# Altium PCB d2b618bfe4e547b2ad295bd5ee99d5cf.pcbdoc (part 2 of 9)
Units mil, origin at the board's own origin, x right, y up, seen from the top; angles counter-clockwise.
Board outline 5129 x 4161 mil, 8 copper layers (Top Layer, GND1, 内层2, VCC, 内层4, Inner5, GND2, Bottom Layer); 491 components, 452 nets, 2562 pads, 1124 vias.
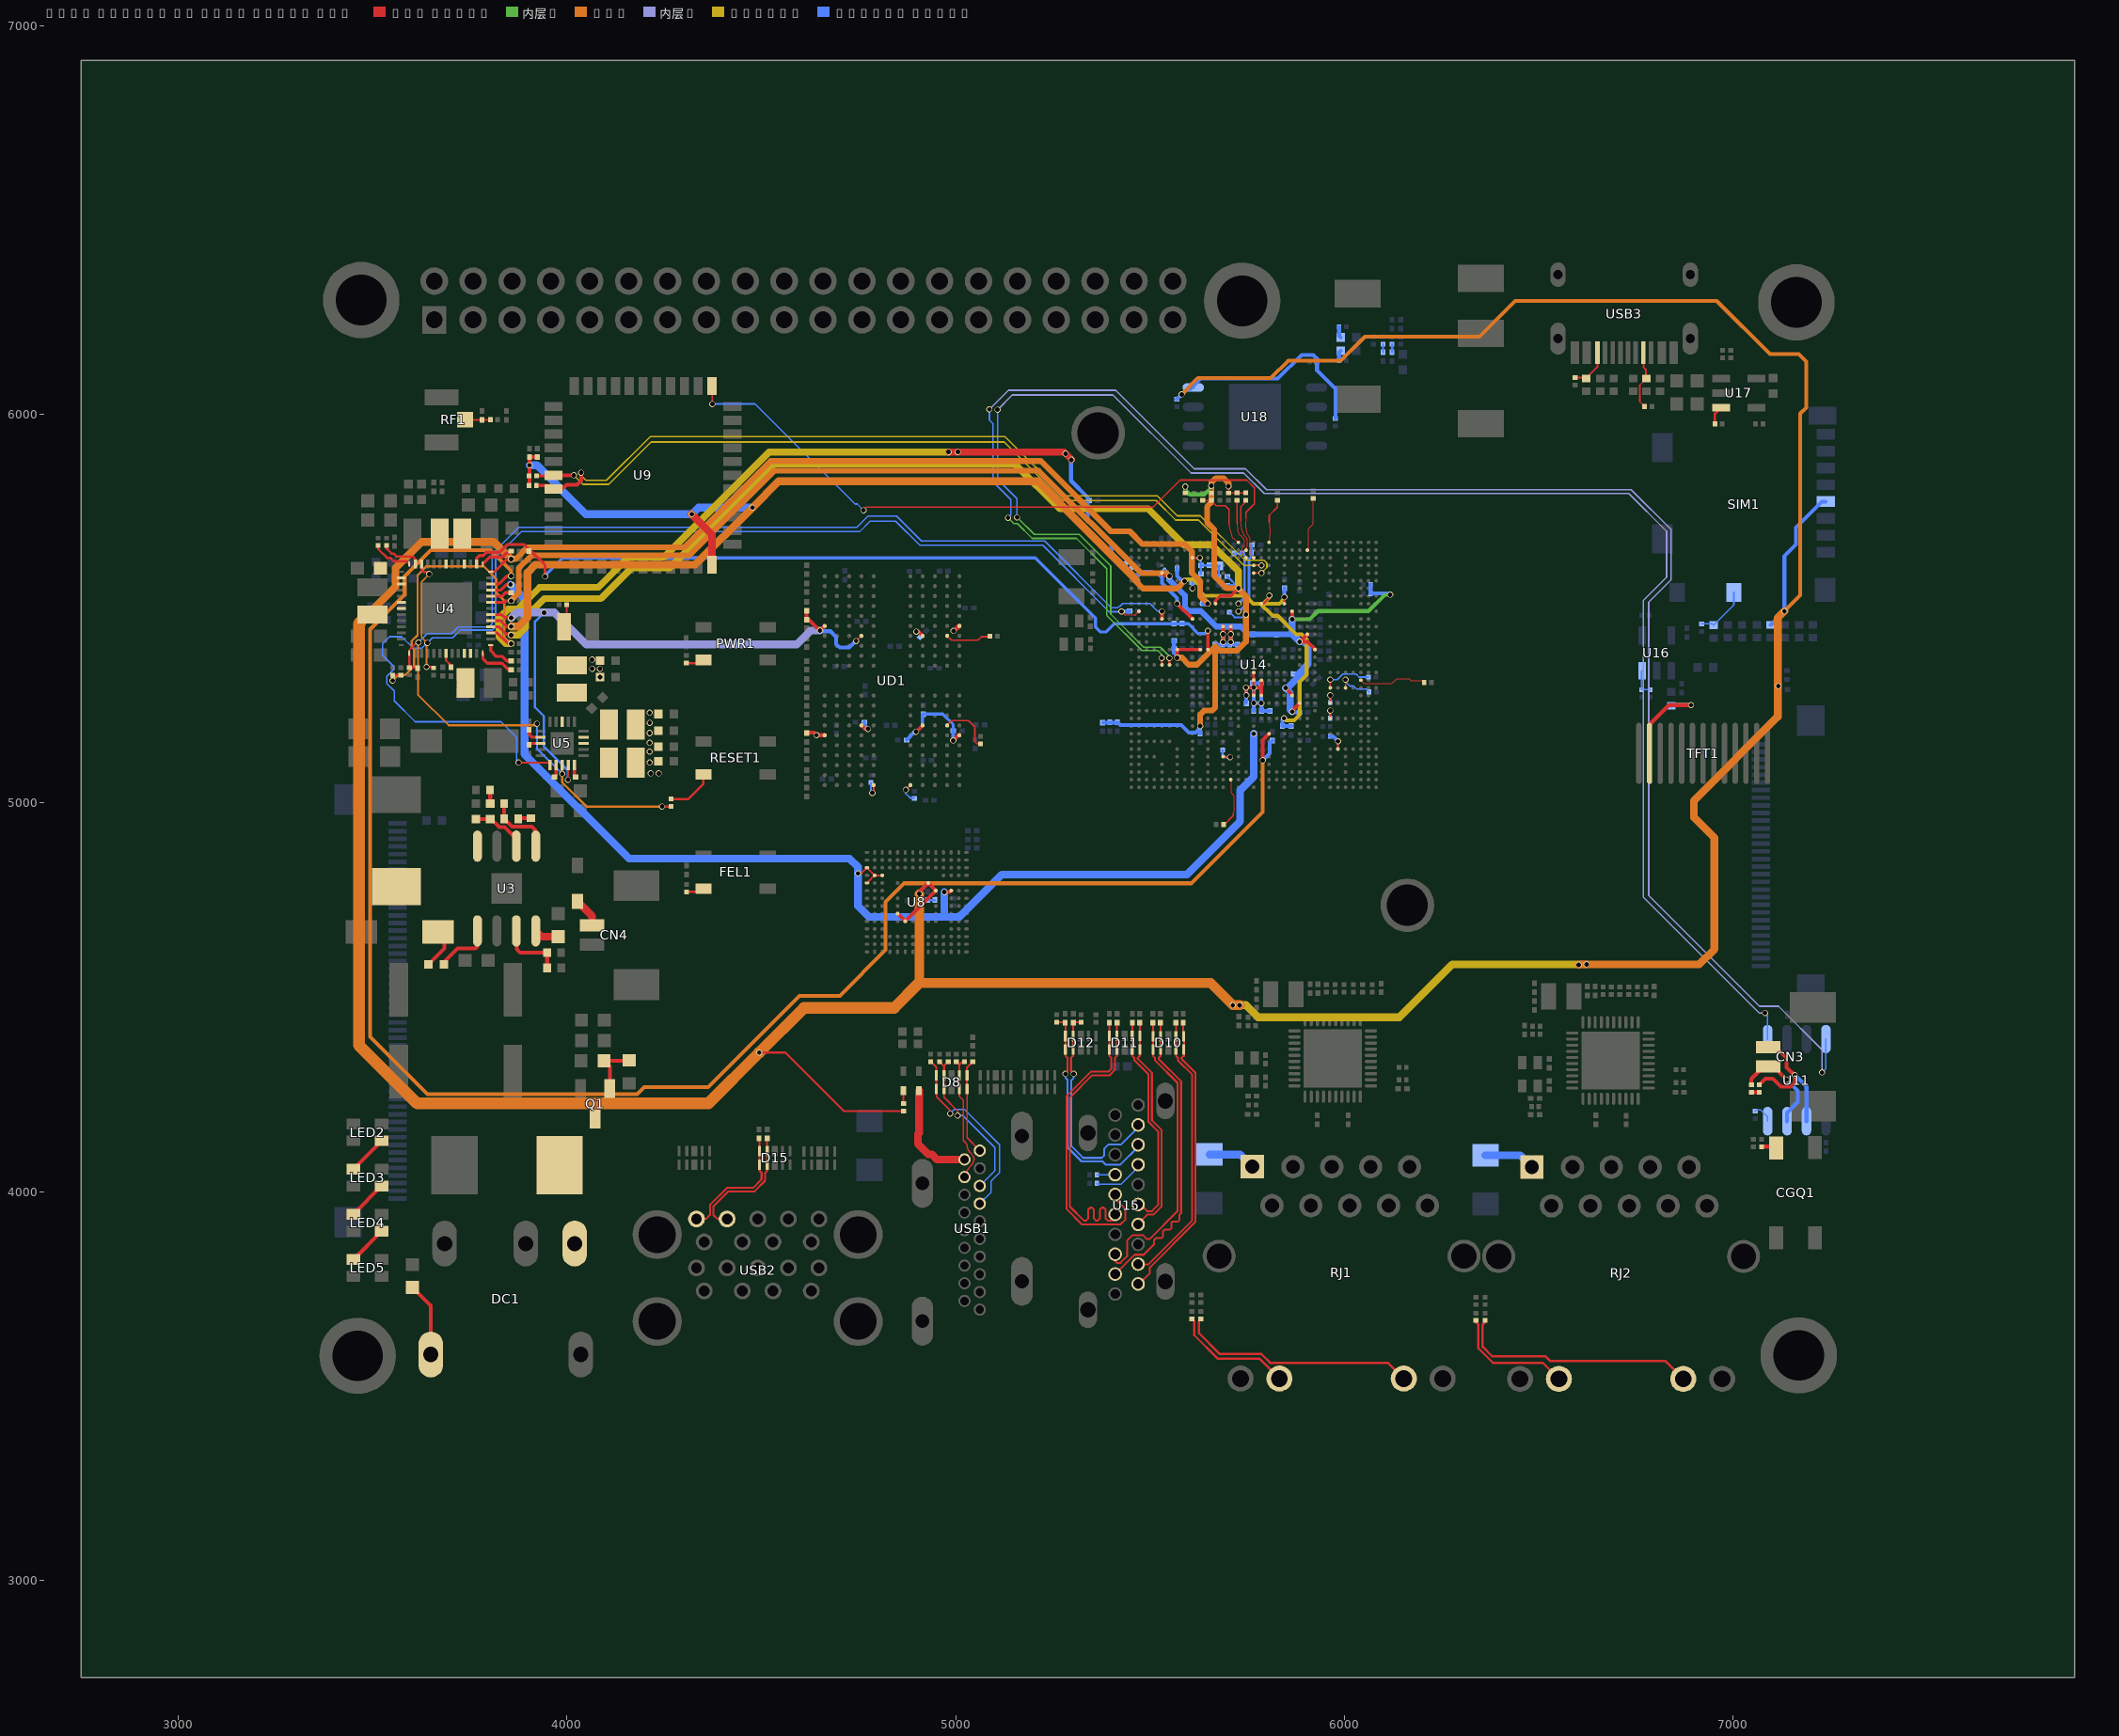
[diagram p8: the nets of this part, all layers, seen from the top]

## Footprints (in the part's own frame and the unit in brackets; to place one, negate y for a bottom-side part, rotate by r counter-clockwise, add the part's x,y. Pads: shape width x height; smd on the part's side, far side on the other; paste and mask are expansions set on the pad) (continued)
SOD-323_L1.8-W1.3-LS2.5-RD [mm]
  rect 1x0.75 smd: 1(-1.173,0) 2(1.173,0)
  silkscreen extent -1.08,-0.8 0.9,0.8
"SOD-523_L1.2-W0.8-LS1.6-RD-1 NSK" [mm]
  rect 0.6x0.36 smd: 1(-0.635,0) 2(0.635,0)
  silkscreen extent -0.13,-0.13 -0.13,0.13
SOIC-8_L5.0-W4.0-P1.27-LS6.0-BL-EP2.0 [mm]
  oval 0.574x2.038 smd: 1(-1.905,-2.769) 2(-0.635,-2.769) 3(0.635,-2.769) 4(1.905,-2.769) 5(1.905,2.769) 6(0.635,2.769) 7(-0.635,2.769) 8(-1.905,2.769)
  rect 2x2 smd: 9(0,0)
  silkscreen extent -2.79,-2.92 2.53,1.52
SOP-8_L4.9-W3.9-P1.27-LS6.0-BL [mm]
  oval 0.63x1.865 smd: 1(-1.905,-2.682) 2(-0.635,-2.682) 3(0.635,-2.682) 4(1.905,-2.682) 5(1.905,2.682) 6(0.635,2.682) 7(-0.635,2.682) 8(-1.905,2.682)
  silkscreen extent -2.82,-2.83 2.58,1.52
SOT-23-3_L2.9-W1.3-P1.90-LS2.4-BR [mm]
  rect 1.25x0.7 smd: 1(1,-0.95) 2(1,0.95) 3(-1,0)
  silkscreen extent -0.73,-1.53 0.73,1.53
SOT-23-5_L3.0-W1.7-P0.95-LS2.8-BL [mm]
  rect 0.49x1.157 smd: 1(-0.95,-1.154) 2(0,-1.154) 3(0.95,-1.154)
  rect 0.49x1.175 smd: 4(0.95,1.154) 5(-0.95,1.154)
  silkscreen extent -1.8,-1.29 1.53,0.85
SW-SMD_4P-L4.2-W3.4-P2.15-LS4.5-TL [mm]
  rect 1.05x0.7 smd: 1(-2.1,1.075) 2(2.1,1.075) 3(-2.1,-1.075) 4(2.1,-1.075)
  silkscreen extent -2.2,-1.69 2.2,1.71
T527-BGA664 [mm]
  round 0.239 smd: A1(-8,8) A2(-7.5,8) A3(-7,8) A4(-6.5,8) A5(-6,8) A6(-5.5,8) A8(-4.5,8) A10(-3.5,8) A12(-2.5,8) A14(-1.5,8) A16(-0.5,8) A18(0.5,8) A20(1.5,8) A22(2.5,8) A24(3.5,8) A26(4.5,8) A28(5.5,8) A29(6,8) A30(6.5,8) A31(7,8) A32(7.5,8) A33(8,8) AA1(-8,-2) AA2(-7.5,-2) AA3(-7,-2) AA4(-6.5,-2) AA5(-6,-2) AA6(-5.5,-2) AA7(-5,-2) AA9(-4,-2) AA12(-2.5,-2) AA13(-2,-2) AA15(-1,-2) AA16(-0.5,-2) AA18(0.5,-2) AA19(1,-2) AA21(2,-2) AA22(2.5,-2) AA24(3.5,-2) AA26(4.5,-2) AA27(5,-2) AA28(5.5,-2) AA29(6,-2) AA30(6.5,-2) AA31(7,-2) AA32(7.5,-2) AA33(8,-2) AB2(-7.5,-2.5) AB3(-7,-2.5) AB9(-4,-2.5) AB10(-3.5,-2.5) AB11(-3,-2.5) AB12(-2.5,-2.5) AB13(-2,-2.5) AB14(-1.5,-2.5) AB15(-1,-2.5) AB17(0,-2.5) AB24(3.5,-2.5) AB32(7.5,-2.5) AB33(8,-2.5) AC1(-8,-3) AC2(-7.5,-3) AC3(-7,-3) AC4(-6.5,-3) AC5(-6,-3) AC6(-5.5,-3) AC7(-5,-3) AC9(-4,-3) AC15(-1,-3) AC17(0,-3) AC18(0.5,-3) AC19(1,-3) AC20(1.5,-3) AC22(2.5,-3) AC24(3.5,-3) AC26(4.5,-3) AC27(5,-3) AC28(5.5,-3) AC29(6,-3) AC30(6.5,-3) AC31(7,-3) AC32(7.5,-3) AC33(8,-3) AD1(-8,-3.5) AD2(-7.5,-3.5) AD9(-4,-3.5) AD11(-3,-3.5) AD13(-2,-3.5) AD14(-1.5,-3.5) AD15(-1,-3.5) AD20(1.5,-3.5) AD21(2,-3.5) AD22(2.5,-3.5) AD25(4,-3.5) AD32(7.5,-3.5) AD33(8,-3.5) AE1(-8,-4) AE2(-7.5,-4) AE3(-7,-4) AE4(-6.5,-4) AE5(-6,-4) AE6(-5.5,-4) AE7(-5,-4) AE9(-4,-4) AE11(-3,-4) AE12(-2.5,-4) AE13(-2,-4) AE14(-1.5,-4) AE16(-0.5,-4) AE18(0.5,-4) AE19(1,-4) AE20(1.5,-4) AE21(2,-4) AE22(2.5,-4) AE23(3,-4) AE24(3.5,-4) AE25(4,-4) AE26(4.5,-4) AE27(5,-4) AE28(5.5,-4) AE29(6,-4) AE30(6.5,-4) AE31(7,-4) AE32(7.5,-4) AE33(8,-4) AF1(-8,-4.5) AF2(-7.5,-4.5) AF32(7.5,-4.5) AF33(8,-4.5) AG1(-8,-5) AG2(-7.5,-5) AG3(-7,-5) AG4(-6.5,-5) AG5(-6,-5) AG6(-5.5,-5) AG7(-5,-5) AG9(-4,-5) AG11(-3,-5) AG13(-2,-5) AG15(-1,-5) AG17(0,-5) AG19(1,-5) AG21(2,-5) AG23(3,-5) AG25(4,-5) AG28(5.5,-5) AG29(6,-5) AG30(6.5,-5) AG31(7,-5) AG32(7.5,-5) AG33(8,-5) AH1(-8,-5.5) AH2(-7.5,-5.5) AH7(-5,-5.5) AH9(-4,-5.5) AH11(-3,-5.5) AH13(-2,-5.5) AH15(-1,-5.5) AH17(0,-5.5) AH19(1,-5.5) AH21(2,-5.5) AH23(3,-5.5) AH25(4,-5.5) AH27(5,-5.5) AH32(7.5,-5.5) AH33(8,-5.5) AJ1(-8,-6) AJ2(-7.5,-6) AJ3(-7,-6) AJ4(-6.5,-6) AJ5(-6,-6) AJ7(-5,-6) AJ9(-4,-6) AJ11(-3,-6) AJ13(-2,-6) AJ15(-1,-6) AJ17(0,-6) AJ19(1,-6) AJ21(2,-6) AJ23(3,-6) AJ25(4,-6) AJ27(5,-6) AJ30(6.5,-6) AJ31(7,-6) AJ32(7.5,-6) AJ33(8,-6) AK1(-8,-6.5) AK2(-7.5,-6.5) AK5(-6,-6.5) AK7(-5,-6.5) AK9(-4,-6.5) AK11(-3,-6.5) AK13(-2,-6.5) AK15(-1,-6.5) AK17(0,-6.5) AK19(1,-6.5) AK21(2,-6.5) AK23(3,-6.5) AK25(4,-6.5) AK27(5,-6.5) AK29(6,-6.5) AK32(7.5,-6.5) AK33(8,-6.5) AL1(-8,-7) AL2(-7.5,-7) AL3(-7,-7) AL5(-6,-7) AL7(-5,-7) AL9(-4,-7) AL11(-3,-7) AL12(-2.5,-7) AL13(-2,-7) AL14(-1.5,-7) AL15(-1,-7) AL16(-0.5,-7) AL17(0,-7) AL19(1,-7) AL21(2,-7) AL23(3,-7) AL25(4,-7) AL27(5,-7) AL29(6,-7) AL31(7,-7) AL32(7.5,-7) AL33(8,-7) AM1(-8,-7.5) AM2(-7.5,-7.5) AM3(-7,-7.5) AM4(-6.5,-7.5) AM5(-6,-7.5) AM6(-5.5,-7.5) AM7(-5,-7.5) AM8(-4.5,-7.5) AM9(-4,-7.5) AM10(-3.5,-7.5) AM11(-3,-7.5) AM12(-2.5,-7.5) AM13(-2,-7.5) AM14(-1.5,-7.5) AM15(-1,-7.5) AM16(-0.5,-7.5) AM17(0,-7.5) AM18(0.5,-7.5) AM19(1,-7.5) AM20(1.5,-7.5) AM21(2,-7.5) AM22(2.5,-7.5) AM23(3,-7.5) AM24(3.5,-7.5) AM25(4,-7.5) AM26(4.5,-7.5) AM27(5,-7.5) AM28(5.5,-7.5) AM29(6,-7.5) AM30(6.5,-7.5) AM31(7,-7.5) AM32(7.5,-7.5) AM33(8,-7.5) AN1(-8,-8) AN2(-7.5,-8) AN3(-7,-8) AN4(-6.5,-8) AN5(-6,-8) AN6(-5.5,-8) AN7(-5,-8) AN8(-4.5,-8) AN9(-4,-8) AN10(-3.5,-8) AN11(-3,-8) AN13(-2,-8) AN15(-1,-8) AN17(0,-8) AN18(0.5,-8) AN19(1,-8) AN20(1.5,-8) AN21(2,-8) AN22(2.5,-8) AN23(3,-8) AN24(3.5,-8) AN25(4,-8) AN26(4.5,-8) AN27(5,-8) AN28(5.5,-8) AN29(6,-8) AN30(6.5,-8) AN31(7,-8) AN32(7.5,-8) AN33(8,-8) B1(-8,7.5) B2(-7.5,7.5) B3(-7,7.5) B4(-6.5,7.5) B5(-6,7.5) B6(-5.5,7.5) B7(-5,7.5) B8(-4.5,7.5) B9(-4,7.5) B10(-3.5,7.5) B11(-3,7.5) B12(-2.5,7.5) B13(-2,7.5) B14(-1.5,7.5) B15(-1,7.5) B16(-0.5,7.5) B17(0,7.5) B18(0.5,7.5) B19(1,7.5) B20(1.5,7.5) B21(2,7.5) B22(2.5,7.5) B23(3,7.5) B24(3.5,7.5) B25(4,7.5) B26(4.5,7.5) B27(5,7.5) B28(5.5,7.5) B29(6,7.5) B30(6.5,7.5) B31(7,7.5) B32(7.5,7.5) B33(8,7.5) C1(-8,7) C2(-7.5,7) C3(-7,7) C4(-6.5,7) C6(-5.5,7) C7(-5,7) C8(-4.5,7) C9(-4,7) C10(-3.5,7) C11(-3,7) C12(-2.5,7) C13(-2,7) C14(-1.5,7) C15(-1,7) C16(-0.5,7) C17(0,7) C18(0.5,7) C19(1,7) C20(1.5,7) C21(2,7) C22(2.5,7) C23(3,7) C24(3.5,7) C25(4,7) C26(4.5,7) C27(5,7) C28(5.5,7) C29(6,7) C30(6.5,7) C31(7,7) C32(7.5,7) C33(8,7) D1(-8,6.5) D2(-7.5,6.5) D6(-5.5,6.5) D8(-4.5,6.5) D10(-3.5,6.5) D12(-2.5,6.5) D14(-1.5,6.5) D16(-0.5,6.5) D18(0.5,6.5) D20(1.5,6.5) D22(2.5,6.5) D24(3.5,6.5) D26(4.5,6.5) D28(5.5,6.5) D32(7.5,6.5) D33(8,6.5) E1(-8,6) E2(-7.5,6) E3(-7,6) E4(-6.5,6) E5(-6,6) E6(-5.5,6) E8(-4.5,6) E10(-3.5,6) E12(-2.5,6) E14(-1.5,6) E16(-0.5,6) E18(0.5,6) E20(1.5,6) E22(2.5,6) E24(3.5,6) E26(4.5,6) E28(5.5,6) E29(6,6) E30(6.5,6) E31(7,6) E32(7.5,6) E33(8,6) F1(-8,5.5) F2(-7.5,5.5) F6(-5.5,5.5) F8(-4.5,5.5) F10(-3.5,5.5) F12(-2.5,5.5) F14(-1.5,5.5) F16(-0.5,5.5) F18(0.5,5.5) F20(1.5,5.5) F22(2.5,5.5) F24(3.5,5.5) F26(4.5,5.5) F28(5.5,5.5) F32(7.5,5.5) F33(8,5.5) G1(-8,5) G2(-7.5,5) G3(-7,5) G4(-6.5,5) G5(-6,5) G6(-5.5,5) G8(-4.5,5) G10(-3.5,5) G12(-2.5,5) G14(-1.5,5) G16(-0.5,5) G18(0.5,5) G20(1.5,5) G22(2.5,5) G24(3.5,5) G26(4.5,5) G28(5.5,5) G29(6,5) G30(6.5,5) G31(7,5) G32(7.5,5) G33(8,5) H2(-7.5,4.5) H3(-7,4.5) H24(3.5,4.5) H31(7,4.5) H32(7.5,4.5) J1(-8,4) J2(-7.5,4) J3(-7,4) J4(-6.5,4) J5(-6,4) J6(-5.5,4) J7(-5,4) J9(-4,4) J10(-3.5,4) J12(-2.5,4) J13(-2,4) J15(-1,4) J16(-0.5,4) J17(0,4) J18(0.5,4) J19(1,4) J21(2,4) J22(2.5,4) J23(3,4) J26(4.5,4) J28(5.5,4) J29(6,4) J30(6.5,4) J31(7,4) J32(7.5,4) J33(8,4) K2(-7.5,3.5) K3(-7,3.5) K9(-4,3.5) K10(-3.5,3.5) K11(-3,3.5) K12(-2.5,3.5) K13(-2,3.5) K15(-1,3.5) K16(-0.5,3.5) K19(1,3.5) K21(2,3.5) K22(2.5,3.5) K24(3.5,3.5) K25(4,3.5) K26(4.5,3.5) K31(7,3.5) K32(7.5,3.5) L1(-8,3) L2(-7.5,3) L3(-7,3) L4(-6.5,3) L5(-6,3) L6(-5.5,3) L7(-5,3) L9(-4,3) L10(-3.5,3) L12(-2.5,3) L13(-2,3) L15(-1,3) L16(-0.5,3) L17(0,3) L18(0.5,3) L19(1,3) L21(2,3) L22(2.5,3) L24(3.5,3) L26(4.5,3) L27(5,3) L28(5.5,3) L29(6,3) L30(6.5,3) L31(7,3) L32(7.5,3) L33(8,3) M2(-7.5,2.5) M3(-7,2.5) M10(-3.5,2.5) M13(-2,2.5) M16(-0.5,2.5) M18(0.5,2.5) M19(1,2.5) M21(2,2.5) M22(2.5,2.5) M31(7,2.5) M32(7.5,2.5) N1(-8,2) N2(-7.5,2) N3(-7,2) N4(-6.5,2) N5(-6,2) N6(-5.5,2) N7(-5,2) N9(-4,2) N10(-3.5,2) N12(-2.5,2) N13(-2,2) N15(-1,2) N18(0.5,2) N19(1,2) N21(2,2) N22(2.5,2) N24(3.5,2) N26(4.5,2) N27(5,2) N28(5.5,2) N29(6,2) N30(6.5,2) N31(7,2) N32(7.5,2) N33(8,2) P2(-7.5,1.5) P3(-7,1.5) P9(-4,1.5) P11(-3,1.5) P13(-2,1.5) P16(-0.5,1.5) P18(0.5,1.5) P19(1,1.5) P21(2,1.5) P22(2.5,1.5) P24(3.5,1.5) P31(7,1.5) P32(7.5,1.5) R1(-8,1) R2(-7.5,1) R3(-7,1) R4(-6.5,1) R5(-6,1) R6(-5.5,1) R7(-5,1) R11(-3,1) R13(-2,1) R15(-1,1) R17(0,1) R18(0.5,1) R19(1,1) R22(2.5,1) R24(3.5,1) R26(4.5,1) R27(5,1) R28(5.5,1) R29(6,1) R30(6.5,1) R31(7,1) R32(7.5,1) R33(8,1) T2(-7.5,0.5) T3(-7,0.5) T9(-4,0.5) T11(-3,0.5) T13(-2,0.5) T15(-1,0.5) T16(-0.5,0.5) T18(0.5,0.5) T19(1,0.5) T21(2,0.5) T22(2.5,0.5) T24(3.5,0.5) T31(7,0.5) T32(7.5,0.5) U1(-8,0) U2(-7.5,0) U3(-7,0) U4(-6.5,0) U5(-6,0) U6(-5.5,0) U7(-5,0) U8(-4.5,0) U10(-3.5,0) U12(-2.5,0) U13(-2,0) U14(-1.5,0) U16(-0.5,0) U18(0.5,0) U19(1,0) U21(2,0) U22(2.5,0) U25(4,0) U26(4.5,0) U27(5,0) U28(5.5,0) U29(6,0) U30(6.5,0) U31(7,0) U32(7.5,0) U33(8,0) V2(-7.5,-0.5) V3(-7,-0.5) V18(0.5,-0.5) V19(1,-0.5) V31(7,-0.5) V32(7.5,-0.5) W1(-8,-1) W2(-7.5,-1) W3(-7,-1) W4(-6.5,-1) W5(-6,-1) W6(-5.5,-1) W7(-5,-1) W9(-4,-1) W10(-3.5,-1) W12(-2.5,-1) W13(-2,-1) W15(-1,-1) W16(-0.5,-1) W19(1,-1) W21(2,-1) W22(2.5,-1) W23(3,-1) W24(3.5,-1) W25(4,-1) W27(5,-1) W28(5.5,-1) W29(6,-1) W30(6.5,-1) W31(7,-1) W32(7.5,-1) W33(8,-1) Y2(-7.5,-1.5) Y3(-7,-1.5) Y9(-4,-1.5) Y10(-3.5,-1.5) Y12(-2.5,-1.5) Y13(-2,-1.5) Y15(-1,-1.5) Y18(0.5,-1.5) Y19(1,-1.5) Y21(2,-1.5) Y22(2.5,-1.5) Y23(3,-1.5) Y24(3.5,-1.5) Y26(4.5,-1.5) Y31(7,-1.5) Y32(7.5,-1.5)
  silkscreen extent -9.26,-8.55 8.55,9.13
TFT_1.14寸_0.7MM-13P [mm]
  oval 4x0.35 smd: 1(2.65,4.2) 2(2.65,3.5) 3(2.65,2.8) 4(2.65,2.1) 5(2.65,1.4) 6(2.65,0.7) 7(2.65,0) 8(2.65,-0.7) 9(2.65,-1.4) 10(2.65,-2.1) 11(2.65,-2.8) 12(2.65,-3.5) 13(2.65,-4.2)
  silkscreen extent -15.5,-8.8 15.5,8.8
USB-A-TH_XUNPU_USB-303WSD-BRY [mm]
  round 1.1 hole 0.7: 1(-3.5,-1.35) 2(-1,-1.35) 3(1,-1.35) 4(3.5,-1.35) 5(4,0.15) 6(2,0.15) 7(0,0.15) 8(-2,0.15) 9(-4,0.15) 10(-3.5,1.85) 11(-1,1.85) 12(1,1.85) 13(3.5,1.85) 14(4,3.35) 15(2,3.35) 16(0,3.35) 17(-2,3.35) 18(-4,3.35)
  round 3.2 hole 2.4: 19(6.57,-3.35) 20(6.57,2.33) 21(-6.57,2.33) 22(-6.57,-3.35)
  silkscreen extent -7.26,-12.97 7.19,4.7
USB-C-SMD_TYPEC-304-BCP16-1 [mm]
  oval 1x2.1 hole 0.6 slot 1.7 at 90 deg: 12(-4.32,1.633) 13(4.32,1.633)
  oval 1x1.6 hole 0.6 slot 1.2 at 90 deg: 14(-4.32,-2.547) 15(4.32,-2.547)
  rect 0.55x1.45 smd: A1B12(-3.225,2.547) A4B9(-2.45,2.547) B1A12(3.225,2.547) B4A9(2.45,2.547)
  rect 0.3x1.45 smd: A5(-1.25,2.547) A6(-0.25,2.547) A7(0.25,2.547) A8(1.25,2.547) B5(1.75,2.547) B6(0.75,2.547) B7(-0.75,2.547) B8(-1.75,2.547)
  Multi-Layer board cut-out: -3.215,1.102 -3.169,0.943 -3.051,0.826 -2.89,0.784 -2.729,0.826 -2.611,0.943 -2.565,1.102 -2.565,1.102 -2.611,1.262 -2.729,1.378 -2.89,1.421 -3.051,1.379 -3.169,1.262 -3.215,1.102
  Multi-Layer board cut-out: 2.565,1.102 2.611,0.943 2.729,0.826 2.89,0.784 3.051,0.826 3.169,0.943 3.215,1.102 3.215,1.102 3.169,1.262 3.051,1.378 2.89,1.421 2.729,1.379 2.611,1.262 2.565,1.102
  Multi-Layer keep-out circle w0.254: c-2.89,1.102 r0.325
  Multi-Layer keep-out circle w0.254: c2.89,1.102 r0.325
  silkscreen extent -4.4,-5.15 4.4,0.41
WQFN-40_L5.0-W5.0-P0.4-BL-EP [mm]
  oval 0.2x0.8 smd: 1(-1.801,-2.499) 2(-1.4,-2.499) 3(-1.001,-2.499) 4(-0.599,-2.499) 5(-0.201,-2.499) 6(0.201,-2.499) 7(0.599,-2.499) 8(1.001,-2.499) 9(1.4,-2.499) 10(1.801,-2.499) 21(1.801,2.499) 22(1.4,2.499) 23(1.001,2.499) 24(0.599,2.499) 25(0.201,2.499) 26(-0.201,2.499) 27(-0.599,2.499) 28(-1.001,2.499) 29(-1.4,2.499) 30(-1.801,2.499)
  oval 0.8x0.2 smd: 11(2.499,-1.801) 12(2.499,-1.4) 13(2.499,-1.001) 14(2.499,-0.599) 15(2.499,-0.201) 16(2.499,0.201) 17(2.499,0.599) 18(2.499,1.001) 19(2.499,1.4) 20(2.499,1.801) 31(-2.499,1.801) 32(-2.499,1.4) 33(-2.499,1.001) 34(-2.499,0.599) 35(-2.499,0.201) 36(-2.499,-0.201) 37(-2.499,-0.599) 38(-2.499,-1.001) 39(-2.499,-1.4) 40(-2.499,-1.801)
  rect 3.8x3.8 smd: 41(0,0)
  silkscreen extent -2.7,-3.35 2.7,2.7
WSON-8_L8.0-W6.10-P1.27-BL-EP [mm]
  oval 0.56x1.4 smd: 1(-1.905,-4.027) 2(-0.635,-4.027) 3(0.635,-4.027) 4(1.905,-4.027) 5(1.905,4.027) 6(0.635,4.027) 7(-0.635,4.027) 8(-1.905,4.027)
  rect 4.3x3.4 smd: 9(0,0)
  silkscreen extent -3.08,-4.98 3.08,4.08

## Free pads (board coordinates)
  round 196.85 hole 129.92: 54(3462,3578) 54(3471,6294) 54(5737,6292) 54(7163,6288) 54(7169,3579)

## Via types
v1: diameter 15.75, hole 11.8, Top Layer to Bottom Layer, 497 vias
v2: diameter 15.7, hole 11.8, Top Layer to Bottom Layer, 335 vias
v3: diameter 15.75, hole 11.81, Top Layer to Bottom Layer, 279 vias
v4: diameter 24, hole 12, Top Layer to Bottom Layer, 13 vias

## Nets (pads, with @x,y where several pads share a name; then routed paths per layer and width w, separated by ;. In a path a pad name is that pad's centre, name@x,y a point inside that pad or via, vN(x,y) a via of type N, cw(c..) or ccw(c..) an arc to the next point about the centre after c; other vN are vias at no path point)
323-ALDO1: C69.1 U5.15 | length 32.4
  Top Layer w8: U5.15@4019.34,5098.08 4019.34,5070.16 C69.1@4022.5,5067
323-DCDC1/2: C19.1 C20.1 C21.1 C22.1 C23.1 C24.1 C72.2 C74.2 C80.2 C81.2 L6.2 L7.2 U14.T19 U14.T21 U14.T22 U14.U18 U14.U19 U14.U21 U14.U22 | length 430
  Top Layer w8: v2(5748,5277) 5748,5296 v2(5747,5297) v2(5767,5297) ; U14.U21@5766.98,5276.73 v2(5767,5297) ; U14.U18@5766.98,5335.78 U14.U19@5766.98,5316.1 v2(5767,5297) ; U14.T21@5786.67,5276.73 5787,5277.06 5787,5297 ; U14.T19@5786.67,5316.1 5787,5315.76 5787,5297 ; v2(5767,5297) 5787,5297
  Bottom Layer w10: C20.1@5745.5,5257 5748,5259.5 v2(5748,5277) 5748,5296 v2(5747,5297) v2(5767,5297) ; C23.1@5767,5236.5 v2(5766.98,5257.04) ; C21.1@5809,5237 5808.5,5236.5 C22.1@5787,5236.5 5787,5256.71 v2(5786.67,5257.04) ; v2(5766.98,5257.04) v2(5767,5297) ; v2(5766.98,5257.04) v2(5786.67,5257.04) ; v2(5767,5297) 5767,5305.5 C19.1@5764,5308.5 C24.1@5786,5308.5 5786.67,5307.83 v2(5786.67,5257.04)
  other v1: 4216,5076 4236.59,5076 4213,5104 4213,5132.37 4213,5154.8 4213,5180.01 4213,5206.33 4213,5232.09
323-DCDC3: C83.1 C84.1 C85.1 C86.1 C87.2 C89.2 L8.2 U14.AA12 U14.AA13 U14.Y12 U14.Y13 | length 199.1
  Top Layer w10: v2(5688.24,5414.21) v2(5688.24,5434.21) U14.AA12@5688.24,5453.9 ; v2(5707.92,5414.21) v2(5707.92,5434.21) U14.Y12@5707.92,5453.9
  Bottom Layer w10: C84.1@5667.23,5407.31 C83.1@5686.23,5407.31 ; v2(5688.24,5434.21) v2(5688.24,5414.21) 5688.24,5409.32 C83.1@5686.23,5407.31 ; C85.1@5704.99,5407.14 5707.92,5410.07 v2(5707.92,5434.21) ; C86.1@5725.23,5407.31 5714.83,5407.31 v2(5707.92,5414.21) 5701.02,5407.31 C83.1@5686.23,5407.31
  other v1: 4084.95,5323.63 4065,5345.34 4085.38,5345.34 4065,5369
323-DLDO1: C71.1 U5.12 | length 32.6
  Top Layer w8: C71.1@3968.5,5067 3972.09,5070.59 U5.12@3972.09,5098.08
323-RTCLDO: C73.1 U5.7 | length 43.8
  Top Layer w8: C73.1@3903,5188 3903,5177 3911,5169 3932.19,5169 U5.7@3932.43,5169.24
$1N3706: L2.1 U4.10 U4.11
$1N3718: L3.1 U4.33
$1N3723: L4.1 U4.30
$1N3725: C43.1 U4.7 | length 41.6
  Top Layer w6: U4.7@3689.11,5385.61 3689.11,5366.89 3701.75,5354.25 C43.1@3701.75,5349.22
$1N4703: R13.2 U4.39 | length 104.9
  Top Layer w6: R13.2@3514.47,5662.49 3514.47,5653.53 3537,5631 3545.49,5631 3554.49,5622 3587.96,5622 U4.39@3594.63,5615.33
$1N4773: C44.2 U4.41 U4.42
$1N4806: R14.2 U4.38 | length 105.5
  Top Layer w6: R14.2@3536,5662.49 3536,5655 3549,5642 3554,5642 3561.5,5634.5 3603.5,5634.5 3610.37,5627.63 U4.38@3610.37,5615.33
$1N4992: L5.2 U4.45 U4.46
$1N6251: L6.1 U5.18
$1N6517: L7.1 U5.19
$1N6728: L8.1 U5.3
$1N7320: C88.1 U5.8 | length 31.1
  Top Layer w8: C88.1@3903,5149.5 3906.99,5153.49 U5.8@3932.43,5153.49
$1N42597: LED1.1 R17.1 | length 59
  Top Layer w6: LED1.1@3992.63,5453.84 3999.51,5460.73 R17.1@3999.51,5510
$2N1846: R21.1 RESET1.3 | length 123.8
  Top Layer w6: R21.1@4268,5010.51 4312.51,5010.51 4351.32,5049.32 RESET1.3@4351.32,5073.68
$2N2360: R19.1 U14.V3 | length 162.3
  Top Layer w3: 5725.01,5720.45 5726.4,5700.33 5731.46,5688.13 5735.46,5687.29 5743.72,5675.93 5743.82,5663.67 5737.3,5657.15 5737.36,5656.88 5737.36,5640.84 U14.V3@5747.19,5631.01
  Top Layer w4: R19.1@5724.27,5778.76 5724.27,5720.73 5725,5720
$2N2431: R20.1 U14.V2 | length 136.5
  Top Layer w3: 5734,5724.93 5736.55,5705.39 5741.89,5689.5 5750.21,5678.07 5750.31,5665.03 5750.55,5664.3 5750.55,5662.51 U14.V2@5746.51,5651.79
  Top Layer w4: 5734,5725 5734,5762 5746.27,5774.27 R20.1@5746.27,5778.76
$2N32401: FEL1.3 R22.1 | length 46.7
  Top Layer w6: R22.1@4308,4771.49 4343.13,4771.49 FEL1.3@4351.32,4779.68
$2N32457: PWR1.3 R23.1 | length 47.4
  Top Layer w6: R23.1@4307.07,5360.18 4343.82,5360.18 PWR1.3@4351.32,5367.68
$3N7591: R38.1 U14.AA29 | length 51.6
  Top Layer w4.5: U14.AA29@5687.91,5119.12 5688.77,5118.26 v3(5706.21,5118.26)
  Bottom Layer w6: R38.1@5685.92,5135.46 5686.92,5134.46 5686.92,5124.97 5693.63,5118.26 v3(5706.21,5118.26)
$3N7643: R39.1 UD1.A5 | length 53.9
  Top Layer w4.5: v3(4871.92,5033.97) 4883.64,5045.69 UD1.A5@4883.64,5046.54
  Bottom Layer w4.5: v3(4871.92,5033.97) 4871.92,5023.97 4882.76,5013.13 R39.1@4893.92,5013.13
$3N7644: R40.1 UD1.A8 | length 49.9
  Top Layer w4.5: v3(4785.84,5025.97) 4789.16,5029.29 UD1.A8@4789.16,5046.54
  Bottom Layer w4.5: R40.1@4782.21,5052.45 4782.21,5029.6 v3(4785.84,5025.97)
$3N7648: R36.1 UD1.G2 | length 138
  Top Layer w4.5: UD1.G2@4978.13,5200.08 4990.04,5212 5033,5212 5049.92,5195.08 5049.92,5157.63 5054.42,5153.13 R36.1@5064.92,5153.13
$3N7649: R37.1 UD1.T2 | length 119
  Top Layer w4.5: UD1.T2@4978.13,5430.4 4989.56,5418.97 5057.92,5418.97 5066.92,5427.97 5086.08,5427.97 R37.1@5087.92,5429.81
$4N500: R41.2 U14.Y32 | length 129.9
  Top Layer w3: U14.Y32@5709.98,5059.57 5709.98,5025.76 5716.84,5018.9 5716.84,4985.06 5714.63,4973.87
  Top Layer w4: R41.2@5689.66,4944.85 5691.85,4944.85 5714.54,4967.54 5714.54,4974.38
$4N609: R42.1 U14.C19 | length 176.1
  Top Layer w3: U14.C19@6042.49,5316.01 6052.39,5306.11 6121.11,5306.11 6133.9,5318.9 6167.81,5318.9 6172.71,5314 6201.49,5314 R42.1@6205.49,5310
$4N713: R43.1 U14.R1 | length 119
  Top Layer w3: U14.R1@5806.29,5670.41 5807.09,5671.21 5810.05,5698.92 5809.6,5700.66 5807,5723.72 5806.92,5724.41 ; 5807,5722.99 5807.09,5722.9
  Top Layer w4: 5807,5722.99 5807,5723.72 5807,5740 5828,5761 R43.1@5828,5778.49
$5N3909: R123.2 U14.K2 | length 139.1
  Top Layer w3: U14.K2@5904.69,5650.71 5908.43,5654.45 5908.43,5705.75 5920,5717.32 R123.2@5920,5783.49
$6N1044: R44.2 U14.G22 | length 38.7
  Top Layer w4: U14.G22@5963.82,5257.04 v1(5963.82,5277.04)
  Bottom Layer w6: R44.2@5963.49,5258.47 5963.82,5258.8 v1(5963.82,5277.04)
$6N1104: R46.2 U14.G24 | length 39.8
  Top Layer w4: U14.G24@5963.82,5217.67 v1(5963.82,5237.67)
  Bottom Layer w6: R46.2@5963.49,5218 5963.49,5237.33 v1(5963.82,5237.67)
$6N1424: R55.2 U14.F28 | length 45.2
  Top Layer w4: U14.F28@5983.52,5138.93 v1(5983.52,5158.93)
  Bottom Layer w10: R55.2@5963.51,5171.53 5970.91,5171.53 v1(5983.52,5158.93)
$6N1887: R45.1 U14.G20 | length 129
  Top Layer w4: U14.G20@5963.83,5296.4 v1(5963.83,5317.4)
  Bottom Layer w4: v1(5963.83,5317.4) 5981.4,5317.4 5996,5332 6030,5332 6038,5324 R45.1@6062.49,5324
$6N1980: R49.2 U14.E20 | length 97.6
  Top Layer w4: U14.E20@6003.2,5296.41 v1(6003.2,5317.41)
  Bottom Layer w4: v1(6003.2,5317.41) 6003.2,5311.8 6014,5301 6024,5301 6032,5293 6056.49,5293 R49.2@6063.49,5286
$6N3848: D7.2 R47.2 | length 33.5
  Top Layer w5: R47.2@4866,4226.51 D7.2@4866,4260
$6N3980: D8.1 D8.10 R48.2 USB1.13 | length 496.1
  Top Layer w4: D8.1@4950.63,4264.67 4950.63,4244.37 4986,4209 v1(4986,4201)
  Top Layer w5: R48.2@4936,4334.49 4950.63,4319.86 D8.10@4950.63,4299.33 D8.1@4950.63,4264.67
  Bottom Layer w4: v1(4986,4201) 4997,4212 5022,4212 5113,4121 5113,4049 5091,4027 5091,3998.11 USB1.13@5062.26,3969.36
$6N4130: D9.1 USB1.18 | length 274.7
  Top Layer w20: D9.1@4906,4260 4906,4151 4903,4148 4903,4123 4930,4096 4939,4096 4951.97,4083.03 USB1.18@5022.89,4083.03
$6N4341: D8.2 D8.9 R50.2 R52.2 USB1.15 | length 418.4
  Top Layer w4: D8.2@4970.3,4264.67 4970.3,4242.7 5005,4208 v1(5005,4196)
  Top Layer w5: R50.2@4959,4334.49 4970.3,4323.19 ; D8.2@4970.3,4264.67 D8.9@4970.3,4299.33 4970.3,4323.19 ; R52.2@4981,4334.49 4970.3,4323.79 4970.3,4323.19
  Bottom Layer w4: v1(5005,4196) 5019,4196 5101,4114 5101,4053.59 USB1.15@5062.26,4014.85
$6N4352: D8.4 D8.7 R51.2 R53.2 USB1.16 | length 336.3
  Top Layer w4: D8.4@5009.7,4264.67 5009.7,4245.3 5020,4235 5020,4132 5026.32,4125.68 cw(c5011.57,4114.53) 5030,4116 ccw(c5050.64,4117.64) 5036,4103 cw(c4999,4066) 5046,4089 cw(c5033.74,4083) 5046,4077 cw(c5009.34,4094.94) 5040,4068 ccw(c5103.16,4012.51) USB1.16@5022.89,4037.52
  Top Layer w5: R51.2@5002,4334.49 5009.7,4326.79 ; D8.4@5009.7,4264.67 D8.7@5009.7,4299.33 5009.7,4326.79 ; R53.2@5023,4334.49 5017.4,4334.49 5009.7,4326.79
$6N4414: D8.5 D8.6 R54.2 USB1.19 | length 248.4
  Top Layer w4: D8.5@5029.37,4264.68 5029.37,4138.68 USB1.19@5062.26,4105.79
  Top Layer w5: D8.5@5029.37,4264.68 D8.6@5029.37,4299.33 5029.37,4319.86 R54.2@5044,4334.49
$6N5317: C190.2 D10.1 D10.10 U15.1 | length 752.3
  Top Layer w5: U15.1@5469.51,3762.25 5471.41,3762.25 5500.01,3790.85 5500.01,3805.1 5617.01,3922.1 5617.01,4305.81 5581.2,4341.62 5581.2,4344.12 5586.52,4349.45 ; C190.2@5585.6,4435.1 5585.6,4401.06 D10.1@5586.52,4400.14 ; 5587.52,4349.6 D10.1@5587.52,4400.14
$6N5400: C191.2 D10.2 D10.9 U15.3 | length 711.8
  Top Layer w5: U15.3@5469.51,3813.45 5496.45,3813.45 5607.99,3924.99 5607.99,4302.08 5572.18,4337.89 5572.18,4344.12 5566.85,4349.45 D10.9@5566.85,4365.34 ; C191.2@5566.6,4435.1 5566.85,4434.86 D10.2@5566.85,4400.14 D10.9@5566.85,4365.48
$6N5519: C192.2 D10.4 D10.7 U15.4 | length 782.1
  Top Layer w5: U15.4@5410.51,3787.85 5460.51,3837.85 5483.85,3837.85 5511,3865 5511,3876 5516.1,3881.1 5530.1,3881.1 5533.71,3884.71 5533.71,3898.71 5537.32,3902.32 5551.32,3902.32 5554.92,3905.92 5554.92,3919.92 5558.53,3923.53 5572.53,3923.53 5576.14,3927.14 5576.14,3941.14 5580.01,3945.01 5580.01,4283.74 5522.13,4341.62 5522.13,4344.12 5527.45,4349.45 D10.7@5527.45,4365.34 ; C192.2@5526.6,4435.1 5527.45,4434.26 D10.4@5527.45,4400.14 D10.7@5527.45,4365.48
$6N5561: C193.2 D10.5 D10.6 U15.6 | length 778.3
  Top Layer w5: U15.6@5410.51,3839.05 5410.51,3821.35 5415.01,3816.85 5424.01,3816.85 5441.01,3833.85 5441.01,3873.85 5455.36,3888.2 5481.66,3888.2 5491.89,3877.97 5498.97,3877.97 5570.99,3949.99 5570.99,4280.01 5513.11,4337.89 5513.11,4344.12 5507.78,4349.45 D10.6@5507.78,4365.34 ; C193.2@5507.6,4435.1 5507.78,4434.93 D10.5@5507.78,4400.13 D10.6@5507.78,4365.48
$6N5603: C194.2 D11.1 D11.10 U15.7 | length 581.3
  Top Layer w5: U15.7@5469.51,3915.75 5469.51,3917.34 5493.01,3940.84 5508.74,3940.84 5530.01,3962.1 5530.01,4158.85 5505.01,4183.85 5505.01,4305.81 5468.79,4342.03 5468.79,4344.53 5474.11,4349.86 D11.10@5474.11,4365.75 ; C194.2@5473.6,4435.1 5474.1,4434.6 D11.1@5474.1,4400.56 D11.10@5474.1,4365.9
$6N5645: C195.2 D11.2 D11.9 U15.9 | length 561.9
  Top Layer w5: D11.9@5454.44,4365.75 5454.44,4349.86 5459.77,4344.53 5459.77,4338.3 5495.99,4302.08 5495.99,4180.12 5520.99,4155.12 5520.99,3965.84 5505.01,3949.85 5493.01,3949.85 5475.91,3966.95 U15.9@5469.51,3966.95 ; D11.9@5454.43,4365.9 D11.2@5454.43,4400.56 5454.43,4434.93 C195.2@5454.6,4435.1
$6N5687: C196.2 D11.4 D11.7 U15.10 | length 800.3
  Top Layer w5: U15.10@5410.51,3941.35 5410.51,3934.35 5402.01,3925.85 5391.01,3925.85 5386.01,3930.85 5386.01,3953.85 5381.01,3958.85 5376.01,3958.85 5371.01,3953.85 5371.01,3930.85 5366.01,3925.85 5361.01,3925.85 5356.01,3930.85 5356.01,3953.85 5351.01,3958.85 5346.01,3958.85 5341.01,3953.85 5341.01,3930.85 5336.01,3925.85 5330.01,3925.85 5294.01,3961.85 5294.01,4242.1 5351.74,4299.84 5396.74,4299.84 5409.72,4312.81 5409.72,4344.53 5415.04,4349.86 D11.7@5415.04,4365.75 ; D11.7@5415.03,4365.9 D11.4@5415.03,4400.56 5415.03,4434.53 C196.2@5415.6,4435.1
$6N5729: C197.2 D11.5 D11.6 U15.12 | length 804.3
  Top Layer w5: D11.6@5395.37,4365.75 5395.37,4349.86 5400.7,4344.53 5400.7,4316.54 5393.01,4308.85 5348.01,4308.85 5284.99,4245.84 5284.99,3956.01 5325.15,3915.85 5424.01,3915.85 5437.01,3928.85 5437.01,3954.85 5410.51,3981.35 U15.12@5410.51,3992.55 ; D11.6@5395.36,4365.9 D11.5@5395.36,4400.55 5395.36,4434.86 C197.2@5395.6,4435.1
$6N6451: C199.2 D12.2 D12.9 R61.2 U15.17 | length 579.2
  Top Layer w5: v1(5304,4303) 5304,4303.4 5296.97,4310.42 5296.97,4344.46 5302.3,4349.78 D12.2@5302.3,4365.67 D12.9@5302.3,4400.33 5302.3,4434.3 C199.2@5303,4435 5304.49,4436.49 R61.2@5323,4436.49
  Bottom Layer w5: v1(5304,4303) 5304,4292.63 5298,4286.63 5298,4117 5328,4087 5376,4087 5382,4093 5382,4110 5393,4121 5425,4121 5469.5,4165.5 U15.17@5469.5,4171.8
$6N6466: C198.2 D12.1 D12.10 R62.2 U15.15 | length 574.7
  Top Layer w5: R62.2@5260,4436.49 5280.51,4436.49 C198.2@5282,4435 5282.63,4434.37 D12.10@5282.63,4400.33 D12.1@5282.63,4365.67 5282.63,4349.78 5287.96,4344.46 5287.96,4310.42 5283,4305.47 v1(5283,4303)
  Bottom Layer w5: v1(5283,4303) 5283,4292.63 5288,4287.63 5288,4114.25 5324.27,4077.98 5378.02,4077.98 5387,4069 5423,4069 5469.5,4115.5 U15.15@5469.5,4120.7
$6N6553: R57.2 U15.14 | length 47.1
  Bottom Layer w4: R57.2@5363.51,4043.53 5410.14,4043.53 U15.14@5410.5,4043.9
$6N6556: R56.2 U15.13 | length 132.1
  Bottom Layer w4: R56.2@5363.51,4021.53 5366.05,4019 5426,4019 5469.5,4062.5 U15.13@5469.5,4069.5
$6N19248: C220.2 D15.5 D15.6 USB2.18 | length 333
  Top Layer w5: USB2.18@4333.52,3929.89 4357.87,3929.89 4367.98,3940 4367.98,3965.98 4412,4010 4479,4010 4500.96,4031.96 4500.96,4048.46 4495.63,4053.78 D15.6@4495.63,4069.67 D15.5@4495.63,4104.32 4495.63,4135.87 C220.2@4494.25,4137.25
$6N19249: C219.2 D15.4 D15.7 USB2.17 | length 333.2
  Top Layer w5: USB2.17@4412.26,3929.89 4387.11,3929.89 4377,3940 4377,3962.25 4415.73,4000.98 4482.73,4000.98 4509.97,4028.22 4509.97,4048.46 4515.3,4053.78 D15.7@4515.3,4069.67 D15.4@4515.3,4104.33 C219.2@4515.3,4137.2
$6N30377: R117.1 U17.3 | length 48.5
  Top Layer w6: R117.1@6953.26,5975.66 6953.26,6001.84 U17.3@6969.04,6017.62
$8N2040: D16.1 R63.2 SIM1.11 | length 139.3
  Bottom Layer w4: R63.2@6918,5461 6946.4,5461 D16.1@6950,5457.4 7001.91,5509.31 SIM1.11@7001.91,5541.73
$8N6741: LED2.1 LED3.3 | length 102.8
  Top Layer w10: LED3.3@3451.16,4058.17 3523.21,4130.22 LED2.1@3523.21,4131.12
$8N6795: LED3.1 LED4.3 | length 102.8
  Top Layer w10: LED4.3@3451.16,3941.91 3451.16,3942.81 LED3.1@3523.21,4014.86
$8N6805: LED4.1 LED5.3 | length 102.8
  Top Layer w10: LED5.3@3451.16,3825.65 3523.21,3897.7 LED4.1@3523.21,3898.6
$8N9148: R115.2 R116.1 U16.3 | length 71.3
  Bottom Layer w4: U16.3@6766.11,5340.31 6765,5339.2 R116.1@6765,5291.51 R115.2@6787,5291.51
$8N11462: R126.1 TFT1.12 | length 253.2
  Top Layer w10: TFT1.12@6784.2,5128.67 6784.2,5201.2 6835,5252 v2(6892,5252)
  Bottom Layer w10: R126.1@6841,5250 6843,5252 v2(6892,5252)
$10N1043: C248.2 RJ1.P1 | length 123.4
  Bottom Layer w20: C248.2@5653,4095.7 5732.06,4095.7 RJ1.P1@5763.4,4064.36
$10N3488: R79.2 RJ1.12 | length 309.3
  Top Layer w6: R79.2@5608,3672.49 5614,3666.49 5614,3631 5674,3571 5781.16,3571 RJ1.12@5833,3519.16
$10N3497: R80.1 RJ1.13 | length 614
  Top Layer w6: R80.1@5631,3672.49 5631,3671 5626,3666 5626,3636 5680,3582 5787,3582 5809,3560 6112.16,3560 RJ1.13@6153,3519.16
$11N1789: C255.2 RJ2.P1 | length 131.9
  Bottom Layer w20: C255.2@6363,4093.7 6452.3,4093.7 RJ2.P1@6482.4,4063.6
$11N1876: R97.2 RJ2.12 | length 313.9
  Top Layer w6: R97.2@6338.37,3668.61 6338.37,3664.63 6345,3658 6345,3597 6382,3560 6510.4,3560 RJ2.12@6552,3518.4
$11N1882: R98.1 RJ2.13 | length 620.5
  Top Layer w6: R98.1@6362.37,3668.61 6362.37,3664.37 6356,3658 6356,3601 6381,3576 6518,3576 6530,3564 6826.4,3564 RJ2.13@6872,3518.4
$12N612: D2.2 DC1.1 Q1.3
$12N673: Q1.1 R1.1 R2.2 | length 142.2
  Top Layer w10: Q1.1@4110.4,4265.37 4110.4,4322.26 R1.1@4095.66,4337 4159.66,4337 R2.2@4160,4336.66
$12N750: C3.2 DC1.5 | length 191.9
  Top Layer w10: C3.2@3603,3753.47 3650.09,3706.39 DC1.5@3650.09,3581.04
$12N1163: C4.1 U3.1 | length 148.6
  Top Layer w10: C4.1@3683.99,4585 3683.99,4590.99 3719,4626 3765,4626 3770,4631 U3.1@3770,4670.98
$12N1491: C8.2 U3.4 | length 64
  Top Layer w20: U3.4@3920,4670.98 3934.51,4656.47 C8.2@3978,4656.47
$12N1559: C4.2 D4.2 L1.1 U3.8 | length 106.8
  Top Layer w10: C4.2@3643.99,4585 3685,4626.01 3685,4651.57 D4.2@3668.57,4668
$12N1618: C9.1 C10.1 U3.6 | length 144.9
  Top Layer w10: C10.1@3766,4959.01 C9.1@3803,4959.01 3804,4960 3826,4938 3840,4938 3870,4908 U3.6@3870,4889.02
$12N1697: C9.2 R7.1 | length 35.4
  Top Layer w10: R7.1@3802,5034 3803,5032.99 C9.2@3803,4999.01
$12N1966: R3.1 R5.2 | length 33.9
  Top Layer w10: R5.2@3874.85,4959.19 3876.66,4961 R3.1@3908,4961
$12N2016: R5.1 R8.2 U3.5 | length 172.6
  Top Layer w10: R8.2@3838.85,4998.18 R5.1@3838.85,4959.19 3859.04,4939 3910,4939 3920,4929 U3.5@3920,4889.02
$12N2052: R4.1 R6.2 U3.3 | length 168.6
  Top Layer w10: U3.3@3870,4670.98 3871,4669.98 3871,4624 3880.22,4614.78 R6.2@3949.27,4614.78 3949.27,4575.95 R4.1@3949.45,4575.77
$12N3300: CN4.2 D1.1 | length 77.7
  Top Layer w20: D1.1@4027,4746.84 4064.91,4708.92 CN4.2@4064.91,4684.8
$13N975: C245.2 R72.2 RF1.1 | length 65.1
  Top Layer w5: RF1.1@3738.02,5986 3738.24,5986.22 C245.2@3781.57,5986.22 R72.2@3803.06,5986.22
$13N1231: R76.1 U11.8 | length 51.1
  Bottom Layer w4: R76.1@7057,4207.51 7059.49,4210 7071,4210 7089,4192 U11.8@7089,4181.39
$13N1378: R77.1 R78.1 | length 20.1
  Top Layer w10: R77.1@7047.19,4255.75 7067.17,4255.75 R78.1@7067.26,4255.83
$13N1478: CN3.1 R77.2 U11.7 | length 263.9
  Top Layer w10: R77.2@7047.19,4274.77 7047.19,4290.19 7079.2,4322.2 CN3.1@7090.91,4322.2 7103.8,4322.2 v2(7138,4288)
  Bottom Layer w10: v2(7138,4288) 7167,4259 7167,4231 7139,4203 U11.7@7139,4181.39
$13N1485: CN3.2 R78.2 U11.6 | length 373.6
  Top Layer w10: R78.2@7067.26,4274.85 7083.4,4291 7102,4291 7123,4270 7148,4270 7159,4281 v2(7159,4300) 7158,4300 7138,4320 7138,4344 7110.2,4371.8 CN3.2@7090.91,4371.8
  Bottom Layer w10: v2(7159,4300) 7189,4270 U11.6@7189,4181.39
$13N1600: C238.2 R65.1 | length 20.8
  Bottom Layer w5: R65.1@6123.19,6180.04 6123.19,6160.06 C238.2@6123.76,6159.49
$13N1603: C241.2 R66.1 | length 21.5
  Bottom Layer w5: C241.2@6099.76,6159.49 R66.1@6099.76,6180.98
$13N2020: C242.2 R67.2 | length 27.6
  Bottom Layer w10: R67.2@5986.49,6138 5986.49,6159.62 C242.2@5990.72,6163.85
$13N2077: C243.2 R68.2 | length 28.9
  Bottom Layer w10: R68.2@5986.49,6225 5986.49,6202.51 C243.2@5990.99,6198
$13N5258: CGQ1.4 R125.1 | length 38.6
  Top Layer w10: R125.1@7073.62,4115.95 7107.74,4115.95 CGQ1.4@7110.88,4112.8
ADCIN0: C106.2 R26.2 U14.W9 | length 161.6
  Bottom Layer w6: C106.2@5716,5642 5736.51,5642 R26.2@5738,5643.49 5743,5638.49 5743,5528.33
  Bottom Layer w7: v1(5727.62,5512.95) 5743,5528.33
ADCIN1: C107.2 R27.2 U14.W10 | length 186.5
  Bottom Layer w7: v1(5727.61,5493.27) 5730.27,5493.27 5755,5518 5755,5628 5760.49,5633.49 R27.2@5760.49,5644 5760.49,5662.49 C107.2@5762,5664
AGND: C108.1 C109.1 C110.1 C111.1 R28.2 U14.AE3 | length 137
  Top Layer w6: U14.AE3@5609.5,5631.06 v1(5628.5,5631.06)
  Bottom Layer w6: v1(5628.5,5631.06) 5631.25,5628.31 C110.1@5631.25,5611.25 ; C109.1@5631.25,5589.25 C110.1@5631.25,5611.25 ; C108.1@5676.5,5583 R28.2@5676.5,5607.51 ; R28.2@5679,5610 R28.2@5676.5,5607.51 ; C110.1@5631.25,5611.25 5651.75,5611.25 C111.1@5652,5611.5 5672.51,5611.5 R28.2@5676.5,5607.51
ALDO1: C51.1 U4.13 | length 98.3
  Top Layer w8: U4.13@3783.6,5385.61 3784,5385.21 3784,5372 3796,5360 3833,5360 3850,5343 C51.1@3856.5,5343
ALDO2: C52.1 U4.14 | length 77.3
  Top Layer w8: U4.14@3803.97,5405.98 3803.97,5392.03 3819,5377 3834.25,5377 3845.25,5366 C52.1@3856.5,5366
ALDO3: C53.1 C181.2 C182.2 C183.2 C184.2 R11.1 R12.1 U4.16 U14.AE11 U14.AG9 | length 3149.8
  Top Layer w6: v1(3551.77,5315) R11.1@3551.77,5329.26 R12.1@3572.77,5329.26
  Top Layer w8: U4.16@3803.97,5437.48 3821.52,5437.48 3849,5410 v2(3856.5,5410)
  Top Layer w10: v2(5570.13,5512.95) U14.AE11@5609.5,5473.58
  Top Layer w18: v2(4982,5903) v2(5006,5903) 5279,5903 v2(5283,5899) 5298,5884 v2(5298,5883)
  VCC w6: v1(3551.77,5315) 3565.77,5329 3584,5329 3607,5352 3607,5395 3601,5401 3601,5417 3616,5432 3616,5586 3639,5609 3786,5609 3819,5576 3819,5541 3839,5521 3839,5427.5 v2(3856.5,5410)
  Inner5 w18: v2(3856.5,5410) 3843,5410 3826,5427 3826,5476 3849,5499 3874.46,5499 3930.46,5555 4081,5555 4159,5633 4250.46,5633 4520.46,5903 v2(4982,5903)
  Bottom Layer w10: v2(5298,5883) 5297,5882 5297,5829 5340,5786 5340,5730 5401,5669 5401,5644 5459,5586 5471,5586 5480,5595 5505,5595 5510,5590 5521,5590 5531,5580 5531,5566 5570.13,5526.87 v2(5570.13,5512.95)
ALDO4: C54.1 C90.2 C93.2 C108.2 C114.2 C132.1 C133.2 C161.1 C162.2 R19.2 R20.2 R24.2 R30.2 R31.2 R32.2 U4.17 U14.AB9 U14.AD15 U14.AD25 U14.AG15 U14.W7 | length 4078.8
  Top Layer w4: R32.2@5591,5797.51 v1(5591,5814) ; R30.2@5658,5797.51 v1(5658,5816) ; v1(5702,5815) R31.2@5702,5797.51 R19.2@5724,5797.51 ; R19.2@5724.27,5797.78 R19.2@5724,5797.51 ; R20.2@5746.27,5797.78 5746,5797.51 R19.2@5724,5797.51
  Top Layer w8: U4.17@3803.97,5453.23 3825.77,5453.23 3844,5435 3853.5,5435 v2(3856.5,5432) ; U14.AG15@5570.13,5394.83 U14.AD15@5629.18,5394.84 ; U14.AB9@5668.54,5512.95 5668.54,5520.54 5681,5533 5708.29,5533 v1(5727.62,5552.32)
  Top Layer w10: v2(5570,5374) 5570,5394.71 U14.AG15@5570.13,5394.83
  内层2 w10: v1(5591,5814) 5591,5805 5602,5794 5640,5794 5658,5812 v1(5658,5816)
  VCC w15: v2(5570,5374) 5582,5374 5599.89,5356.11 5621.11,5356.11 5668,5403 ; v1(5629.19,5197.99) 5629.19,5228.19 5639,5238 5660,5238 5668,5246 5668,5403 ; v1(5702,5815) 5702,5823 5689,5836 5670,5836 5658,5824 v1(5658,5816) 5658,5773 5647,5762 5647,5722 5665,5704 5665,5585 5697.68,5552.32 v1(5727.62,5552.32) 5747,5532.94 v2(5747,5484.84) 5747,5415 5724,5392 5679,5392 5668,5403
  Inner5 w18: v2@3856.6,5432.1 3856.7,5432 3875,5432 3894,5451 3894,5478 3942,5526 4087,5526 ; 4090,5528 4167,5605 4265.46,5605 4533.46,5873 5152,5873 5268,5757 5495,5757 5587,5665 5659,5665 5727.62,5596.38 v1(5727.62,5552.32)
  Bottom Layer w5: R24.2@5704.51,5491 5717.51,5478 5740.16,5478 v2(5747,5484.84)
  Bottom Layer w6: C108.2@5699,5583 5727.62,5554.38 v1(5727.62,5552.32)
  Bottom Layer w8: C114.2@5699,5560 5719.94,5560 v1(5727.62,5552.32)
  Bottom Layer w10: C162.2@5379.92,5206.47 5380.26,5206.81 C132.1@5417.92,5206.81 ; C132.1@5416.92,5205.81 C132.1@5417.92,5206.81 ; C90.2@5562,5418 C93.2@5562,5397 5562,5385.62 5570,5377.62 v2(5570,5374) ; C133.2@5629,5179 5629.19,5179.19 v1@5629.19,5193.19 ; v1(5629.19,5197.99) v1@5629.19,5193.19 ; C132.1@5417.92,5206.81 5423.76,5200.97 5580.22,5200.97 5600.19,5181 5617,5181 v1@5629.19,5193.19
ALDO-OUT: C103.2 U14.AE7 | length 16.5
  Bottom Layer w7: C103.2@5609,5568 5609,5552.18 5609.18,5552 v1(5609.5,5552.32)
AP-NMI: C94.2 R10.2 U4.37 U5.11 U14.AM10 | length 3321.8
  Top Layer w3: 5436,5483.76 5462,5483.76
  Top Layer w4: v1(5427,5492.76) 5436,5483.76 ; 5462,5483.76 5471.51,5493.26 U14.AM10@5471.7,5493.26
  Top Layer w5: v1(3876,5104) 3950.42,5104 U5.11@3956.34,5098.08
  Top Layer w6: U4.37@3626.12,5615.33 3626.12,5600.4 3632.51,5594 3641,5594 v2(3646,5589) ; v2(3639,5350) 3654.51,5350 R10.2@3657,5347.51
  VCC w4: v2(3641,5412) 3626.2,5426.8 3626.2,5569.2 v2(3646,5589)
  VCC w6: v2(3639,5350) 3639,5410 v2(3641,5412)
  Bottom Layer w4: v1(3876,5104) 3871,5109 3871,5169 3831,5209 3610,5209 3556,5263 3556,5288 3537,5307 3537,5326 3555,5344 3555,5351 3526,5380 3526,5410 3544,5428 3575,5428 3605,5398 3627,5398 v2(3641,5412) 3654,5425 3706,5425 3726,5445 3809,5445 3817,5453 3817,5632 3883,5698 4753,5698 4780,5725 4846,5725 4908,5663 5224,5663 5395,5492 5426.24,5492 v1(5427,5492.76)
  Bottom Layer w10: v1(5427,5492.76) 5445.76,5492.76 C94.2@5447,5494
AP-RESET: C95.2 R9.2 R21.2 U4.1 U5.13 U14.AJ11 | length 3360.8
  Top Layer w4: U4.1@3594.63,5385.61 3594.63,5393.63 3614,5413 v2(3618,5413)
  Top Layer w5: U5.13@3987.84,5098.08 3987.84,5075.16 v1(3988,5075)
  Top Layer w6: U4.1@3594.63,5385.61 3595,5385.24 R9.2@3595,5348.51 3614.49,5348.51 C95.2@3616,5347 ; v2(4245,4991) 4267.51,4991 R21.2@4268,4991.49
  Top Layer w10: U14.AJ11@5530.76,5473.58 5531,5473.82 v1(5531,5493)
  VCC w5: v2(3618,5413) 3617,5412 3617,5279 3696,5200 3919,5200 v2(3923,5204)
  VCC w6: v1(3988,5075) 3988,5053 4050,4991 v2(4245,4991)
  Bottom Layer w4: v2(3618,5413) 3641,5436 3704,5436 3721,5453 3800,5453 3808,5461 3808,5641 3876,5709 4746,5709 4775,5738 4848,5738 4912,5674 5229,5674 5401,5502 5417,5502 5421,5506 5422.96,5506 5429.96,5513 5500,5513 5519,5494 v1@5529,5494
  Bottom Layer w5: v2(3923,5204) 3923,5140 v1(3988,5075)
AP-WAKE-BT: R69.2 U9.6 U14.U4 | length 2074.2
  Top Layer w4: U14.U4@5766.98,5611.39 v1(5786.98,5611.39)
  Top Layer w8: R69.2@3921.79,5841.7 3962.64,5841.7 U9.6@3966.94,5846
  Top Layer w10: U9.6@3965.94,5843 v1(4018,5843)
  Inner5 w4: v1(4018,5843) 4041,5820 4108,5820 4217,5929 5125,5929 5276,5778 5516,5778 5566,5728 5625,5728 5741.61,5611.39 v1(5786.98,5611.39)
AXP717-CC1: D24.2 R130.2 USB3.A5 | length 153.7
  Top Layer w4: R130.2@6772.49,6020 6772.49,6020.51 6760,6033 6760,6075.4 D24.2@6777,6092.4
  Top Layer w5: USB3.A5@6769.21,6158.7 6770,6157.91 6770,6121 6776,6115 D24.2@6776,6092.4
AXP717-CC2: D31.2 R129.2 USB3.B5 | length 108.6
  Top Layer w4: R129.2@6594,6094.51 6619.89,6094.51 D31.2@6622,6092.4
  Top Layer w5: D31.2@6621,6091.4 D31.2@6622,6092.4 6651.1,6121.5 USB3.B5@6651.1,6158.7
BLDO1: C59.1 C165.2 C166.2 C171.2 C172.2 C179.2 C180.2 R69.1 R70.1 U4.18 U9.22 U14.N9 U14.N24 U14.T9 | length 3909.8
  Top Layer w6: U14.T9@5786.67,5512.95 5791.95,5512.95 5807,5528 v1(5807,5534) ; U14.N9@5845.72,5512.95 v1(5845.72,5529.95)
  Top Layer w8: U4.18@3803.97,5468.97 3830.03,5468.97 3845,5454 v2(3856.5,5454)
  Top Layer w10: R70.1@3902.49,5817 3904,5818.51 R69.1@3904,5842.93 ; R69.1@3902.77,5841.7 R69.1@3904,5842.93 ; C179.2@3923.75,5889.75 C180.2@3903.75,5889.75 3904,5889.5 v2(3904,5869) R69.1@3904,5842.93
  Top Layer w20: v2(4321,5743) 4373.17,5690.83 U9.22@4373.17,5612.94
  VCC w15: 5464,5570 5482,5552 5570,5552 v2(5589,5571)
  VCC w20: v2(3856.5,5454) 3875,5454 3898.65,5477.65 3898.65,5593 3918.65,5613 4330,5613 v2(4477,5760) 4545,5828 5210,5828 5464,5574
  Inner5 w10: v2(5589,5571) 5593,5575 5612,5575 5628,5559 5628,5545 5640,5533 5746,5533 5766,5513 5784,5513 ; v1(5807,5534) 5807,5528.34 5791.66,5513 ; v2(5845,5218) 5850,5213 5871,5213 5885,5227 5885,5312 5903,5330 5903,5421.14 5890.14,5434 5876,5434 5828,5482 5815,5482 5784,5513 ; v1(5845.72,5529.95) 5845.72,5525.72 5833,5513 5791.66,5513 ; 5784,5513 5791.66,5513
  Bottom Layer w10: C172.2@5570,5604 5570,5584 5583,5571 v2(5589,5571) ; v2(5845,5218) 5841,5214 C166.2@5841,5198 C171.2@5863,5198 ; v1(5845.72,5529.95) 5846,5530.23 C165.2@5846,5553
  Bottom Layer w20: v2(3904,5869) 3923,5869 4049,5743 v2(4321,5743) 4338,5760 v2(4477,5760)
BLDO2: C61.1 C134.1 C135.2 C136.2 C137.2 C138.2 C139.2 C140.2 C141.2 U4.19 U5.14 UD1.F1 UD1.F12 UD1.G4 UD1.G9 UD1.T4 UD1.T9 UD1.U1 UD1.U12 | length 2047.9
  Top Layer w4: v3(4744,5416.74) UD1.T9@4757.66,5430.4
  Top Layer w5: v1(4003,5060) 4003.59,5060.59 U5.14@4003.59,5098.08
  Top Layer w8: U4.19@3803.97,5484.72 3832.28,5484.72 3840,5477 3855.5,5477 v2(3856.5,5476)
  Top Layer w10: C140.2@4616.92,5180.97 4635.44,5180.97 v3(4641.92,5174.49) UD1.F12@4663.17,5174.49 ; C139.2@4616.92,5495.97 4616.92,5471.47 4622.42,5471.47 4650.05,5443.84 v3(4651.01,5443.84) UD1.U12@4663.17,5455.99 ; UD1.G9@4757.66,5200.08 4766.77,5190.97 4773.92,5190.97 4774.26,5190.63 v3(4774.52,5190.63) ; v3(4898.3,5183.24) 4899.19,5183.24 4915.14,5199.19 UD1.G4@4915.14,5200.08 ; v3(4898.92,5440.97) 4904.57,5440.97 UD1.T4@4915.14,5430.4 ; v3(4993.92,5160.97) 5007.44,5174.49 UD1.F1@5009.63,5174.49
  Top Layer w12: v3(4994.92,5442.72) 4995.17,5442.97 4996.61,5442.97 UD1.U1@5009.63,5455.99
  内层4 w20: v2(3856.5,5476) 3870.5,5490 v2(3941,5490) 3968,5490 4050,5408 4591,5408 4626.84,5443.84 v3(4651.01,5443.84)
  Bottom Layer w6: v2(3941,5490) 3918,5467 3918,5246 3941,5223 3941,5145 4003,5083 v1(4003,5060)
  Bottom Layer w8: v3(4898.3,5183.24) 4915,5199.95 4915,5228.97 4966.92,5228.97 4993.92,5201.97 C138.2@4993.92,5186.97
  Bottom Layer w10: v3@4640.4,5174.49 v3(4641.92,5174.49) ; v3(4651.01,5443.84) 4652.88,5441.97 4677.92,5441.97 4693.01,5426.89 4693.01,5409.07 4702.1,5399.97 4726.92,5399.97 4743.69,5416.74 v3(4744,5416.74) ; C137.2@4764.92,5207.97 4764.92,5200.23 v3(4774.52,5190.63) ; C135.2@4874.92,5162.97 4895.19,5183.24 v3(4898.3,5183.24) ; v3(4993.92,5160.97) C138.2@4993.92,5186.97
BLDO3: C63.1 C104.2 C185.2 C186.2 C187.2 C188.2 C201.2 C202.2 C208.2 C209.2 R127.1 R128.1 U4.21 U14.AJ5 U14.J15 U14.K13 U14.L22 U14.M10 U14.M21 | length 3311.8
  Top Layer w6: U14.AJ5@5530.76,5591.69 5538.45,5584 v1(5550,5584)
  Top Layer w8: U4.21@3803.97,5516.22 3839.22,5516.22 3843,5520 v2(3856.5,5520)
  Top Layer w10: v2(5849,5296) 5865.41,5279.59 U14.M21@5865.41,5276.73 ; U14.M10@5865.41,5493.27 5866,5492.68 v2(5866,5473) ; v2(5866,5235) 5866,5237.94 U14.L22@5885.1,5257.04 ; v2(5885,5415) v2@5885.57,5415 ; U14.K13@5904.78,5434.21 v2@5885.57,5415 ; U14.J15@5924.46,5394.83 5925,5395.37 5905.37,5415 v2@5885.57,5415
  内层2 w10: v2(5866,5473) 5911,5473 5932,5494 6062,5494 6104,5536 v2(6118,5536)
  VCC w15: v2(3856.5,5520) 3876,5539.5 3876,5604 3909,5637 4315,5637 4533,5855 5214,5855 5478,5591 5543,5591 v1(5550,5584)
  Bottom Layer w5: C187.2@5870,5332 5882,5332
  Bottom Layer w10: C202.2@5537.78,5597.22 5537.78,5596.22 v1(5550,5584) ; v2(5866,5235) 5868,5233 C201.2@5884,5233 ; R127.1@6067.51,5562 R128.1@6067.51,5539 6115,5539 v2(6118,5536)
  Bottom Layer w15: v1(5550,5584) 5550,5574 5590,5534 5590,5503 5599,5494 5631,5494 5671,5454 5733.77,5454 5753.77,5434 C208.2@5765,5434 5866,5434
  Bottom Layer w18: v2(5866,5235) 5861,5240 C185.2@5861,5253 C186.2@5861,5272 5861,5284 v2(5849,5296) 5853,5296 5888,5331 ; v2(5866,5473) C104.2@5866,5452 5866,5434 v2(5885,5415) 5896,5415 5907,5404 5907,5357 5882,5332
BLDO4: C65.1 U4.22 | length 56.3
  Top Layer w8: U4.22@3803.97,5531.97 3832.97,5531.97 3842,5541 C65.1@3856.5,5541
BOOT-SEL-ADC: R30.1 R33.2 U14.W1 | length 170.5
  Top Layer w3: 5703.56,5716.97 5712.83,5681.98 U14.W1@5726.58,5671.63
  Top Layer w4: R33.2@5636,5778.49 5656.51,5778.49 R30.1@5658,5777 ; R30.1@5658,5778.49 R30.1@5658,5777 ; 5703.64,5717 5703.64,5755.36 5694,5765 5670,5765 R30.1@5658,5777
BT-RESETN: U9.34 U14.U3 | length 1794.5
  Top Layer w3: 5746.83,5734.69 5745.9,5713.21 5747.83,5695.99 5756.79,5679.77 5757.05,5679.51 5757.05,5640.85 U14.U3@5766.89,5631.01
  Top Layer w4: v2(4374.17,6026.72) U9.34@4374.17,6076.06 ; v1(4763,5753) 4771,5761 5508,5761 5578,5831 5749,5831 5769,5811 5769,5770 5746.96,5747.96 5746.96,5734.04
  Bottom Layer w4: v2(4374.17,6026.72) 4484.28,6026.72 4742,5769 4747,5769 v1(4763,5753)
BT-WAKE-AP: R70.2 U9.7 U14.U5 | length 2158.4
  Top Layer w4: U14.U5@5766.98,5591.69 v1(5786.98,5591.69)
  Top Layer w8: R70.2@3921.51,5817 3960.51,5817 U9.7@3966.94,5810.57
  Top Layer w10: U9.7@3965.94,5807.57 3987.57,5807.57 3999,5819 4026,5819 4037,5830 v1(4037,5850)
  Inner5 w4: v1(4037,5850) 4037,5842 4049,5830 4102,5830 4215,5943 5127,5943 5280,5790 5519,5790 5570,5739 5630,5739 5744,5625 5793,5625 5801,5617 5801,5605.71 v1(5786.98,5591.69)
CAN-RX0: U11.4 U14.AJ17 | length 4589.3
  Top Layer w6: v1(5530,5373) 5530,5356.23 U14.AJ17@5530.76,5355.47
  内层2 w4: v2(5135,5734) 5150,5719 5159,5719 5197,5681 5311,5681 5389,5603 5389,5482.58 5479.58,5392 5520.37,5392 5530,5382.37 v1(5530,5373)
  内层4 w4: v2(5087,6013) 5136,6062 5412,6062 5614,5860 5746,5860 5800,5806 6738,5806 6841,5703 6841,5575 6783,5517 6783,4762 7068,4477 7117,4477 7229,4365 v2(7229,4307)
  Bottom Layer w4: v2(5087,6013) 5087,5985 5096,5976 5096,5827 5142,5781 5142,5741 v2(5135,5734) ; v2(7229,4307) 7239,4317 U11.4@7239,4392.61
CAN-TX0: U11.1 U14.AH17 | length 4287.6
  Top Layer w6: v1(5550,5373) 5550,5355.91 U14.AH17@5550.44,5355.47
  内层2 w4: v2(5158,5735) 5158.34,5735 5202.34,5691 5318,5691 5399,5610 5399,5486 5483.85,5401.15 5526.85,5401.15 5550,5378 v1(5550,5373)
  内层4 w4: v2(5108,6012) 5146,6050 5405,6050 5606,5849 5741,5849 5794,5796 6732,5796 6829,5699 6829,5581 6769,5521 6769,4758 7067,4460 v2(7082,4460)
  Bottom Layer w4: v2(5108,6012) 5108,5833 5158,5783 v2(5158,5735) ; v2(7082,4460) 7089,4453 U11.1@7089,4392.61
CLDO1: C60.2 C163.2 C164.2 C225.1 C226.2 C227.2 U4.23 U8.C6 U8.M4 U8.N4 U8.P3 U8.P5 U14.U26 | length 3110.9
  Top Layer w5: v1(4749,4819) 4757.46,4819 U8.P3@4772.05,4833.59 U8.N4@4791.73,4813.9 ; U8.P5@4772.06,4794.22 U8.N4@4791.73,4813.9 ; U8.M4@4811.41,4813.9 U8.N4@4791.73,4813.9
  Top Layer w8: U4.23@3803.97,5547.71 3829.71,5547.71 3844,5562 v1(3855,5562)
  Top Layer w10: v1(4971,4771) 4985.06,4771 U8.C6@4988.59,4774.52
  Bottom Layer w20: v1(3855,5562) 3891,5526 3891,5126 4160,4857 4727,4857 4749,4835 v1(4749,4819) 4749,4735 4777,4707 4969.22,4707 ; v1(4971,4771) 4971,4708.78 4969.22,4707 ; v1(5766.98,5178.3) 5766.98,5067.98 5732,5033 5732,4953 5595,4816 5119,4816 5010,4707 4969.22,4707
CLDO2: C62.2 C91.2 U4.24 U14.R26 | length 4619.5
  Top Layer w8: U4.24@3803.97,5563.46 3824.46,5563.46 3845,5584 v2(3856.5,5584)
  Top Layer w10: v2(5790,5110) 5790,5161.94 U14.R26@5806.35,5178.3
  VCC w10: v2(3856.5,5584) 3856.5,5597.5 3803.63,5650.37 3650.37,5650.37 3582.63,5582.63 3582.63,5535.58 3493.83,5446.78 3493.83,4398.17 3641,4251 4181,4251 4199,4269 4363.16,4269 4598.16,4504 4702,4504 4820,4622 4820,4746 4867.39,4793.39 5606.39,4793.39 5790,4977 v2(5790,5110)
  Bottom Layer w10: v2(5790,5110) 5808,5128 5808,5154 C91.2@5815,5161
CLDO3: C64.2 C102.2 C228.1 C229.2 C230.2 C234.1 C235.2 C236.2 D20.1 R47.1 R73.2 R74.2 R75.2 SIM1.4 U4.26 U8.E6 U8.F5 U8.J10 U8.K9 U14.AC9 U18.8 | length 12994.8
  Top Layer w5: v2(4495,4358) 4562,4358 4712.51,4207.49 R47.1@4866,4207.49
  Top Layer w8: U4.26@3803.98,5594.97 3813.97,5594.97 3847,5628 v2(3856.5,5628)
  Top Layer w10: U8.K9@4850.78,4715.48 U8.J10@4870.48,4695.78 4945.65,4770.96 ; v2(4907,4766) 4907,4771.69 U8.F5@4929.52,4794.22 4945.65,4778.09 4945.65,4770.96 ; U8.E6@4949.22,4774.52 4945.65,4770.96
  VCC w10: v2(5581.59,6051.1) 5623.49,6093 5811,6093 5856,6138 5991,6138 6053,6200 6348,6200 6440,6292 6958,6292 7095,6155 7169,6155 7188,6136 7188,6017 7173,6002 7173,5534.4 v1(7132,5493.4)
  VCC w15: v2(3856.5,5628) 3869,5628 3899,5658 4302,5658 4524,5880 5219,5880 5400,5699 5448,5699 5481,5666 5589.33,5666 5608,5647.33 5608,5592 5629,5571 5629,5532.82 v2@5648.87,5512.95
  VCC w20: 3470,5467 3559,5556 3559,5605 3625.75,5671.75 3812.75,5671.75 v2(3856.5,5628) ; v2(6603,4584) 6604,4585 v2(6623.08,4585) 6913,4585 6952,4624 6952,4910 6899,4963 6899,5006 7115,5222 7115,5476.4 v1(7132,5493.4)
  VCC w25: v2(4907,4766) 4907,4538 4906,4537 5656,4537 v2(5713,4480) v2(5731,4480)
  VCC w30: 3470,5467 3465,5462 3465,4377 3615,4227 4364,4227 v2(4495,4358) 4610,4473 4842,4473 4906,4537
  Inner5 w20: v2(5713,4480) v2(5731,4480) 5747,4480 5778,4449 6142,4449 6278,4585 v2(6623.08,4585)
  Bottom Layer w6: v2(4907,4766) 4922.75,4750.25 C229.2@4927.75,4750.25 C235.2@4946.75,4750.25 ; v2(7116.5,5301) C228.1@7116.5,5318 C234.1@7116.5,5341
  Bottom Layer w10: C230.2@4899,4749 4899,4758 v2(4907,4766) ; R75.2@5569,6038.51 v2(5581.59,6051.1) 5599.49,6069 U18.8@5607,6069 ; U18.8@5603,6065 U18.8@5607,6069 ; U18.8@5611.23,6069 U18.8@5607,6069 ; C102.2@5636,5513 v2(5648.82,5513) ; R74.2@5977,5989.51 5977,6066 5929.51,6113.49 R73.2@5929.51,6135 5929.51,6143.49 5920,6153 5890,6153 5829,6092 5630,6092 U18.8@5607,6069 ; D20.1@7097,5458.4 v1(7132,5493.4) 7132,5635 7162,5665 7162,5709 7228.4,5775.4 SIM1.4@7238.14,5775.4
CLDO4: C66.2 U4.27 | length 86.4
  Top Layer w8: U4.27@3783.61,5615.33 3801.27,5633 3834,5633 3844,5643 3851.5,5643 C66.2@3856.5,5648
CPUSLDO: C13.1 C14.1 C35.2 U4.28 U14.AC15 | length 2148.2
  Top Layer w8: U4.28@3767.85,5615.33 3768,5615.49 3768,5630 3775,5637 3785,5637 3793,5645 3827,5645 3847,5665 3889.88,5665 3901,5653.88 3901,5649 C35.2@3902,5648 3908,5648 3944,5612 v2(3944,5583) ; U14.AC15@5648.87,5394.84 v2(5648.87,5443)
  Bottom Layer w8: v2(3944,5583) 3944,5586 3989,5631 5205,5631 5360,5476 5360,5453 5373,5440 5387,5440 5408,5461 5599,5461 5624,5436 5641.87,5436 v2(5648.87,5443)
